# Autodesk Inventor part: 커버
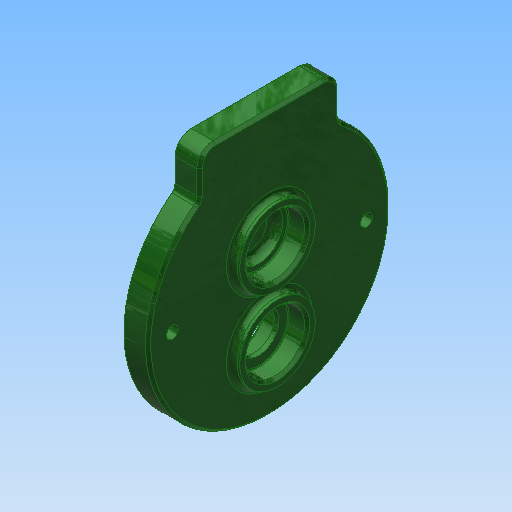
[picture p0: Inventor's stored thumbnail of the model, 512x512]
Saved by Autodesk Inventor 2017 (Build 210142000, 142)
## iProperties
Created: 2016-02
Part Number: 커버
Material: 알루미늄 6061
Document SubType Name: Modeling
Designer: mduedu
Density: 2.71 g/cm^3
Appearance: 매끄러움 - 짙은 산림 녹색
Author: mduedu
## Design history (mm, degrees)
sketch "스케치1"
  geometry: C1 r 45 at (0, 0); 1 further point
  constraints: 1 centre point, 1 coincident
  dimensions: "d0" = 90 diameter of C1
extrude "돌출1" new body sketch "스케치1" distance "d1" = 9; taper "d2" = 0 deg
sketch "스케치2"
  geometry: C1 r 14 at (0, 11); 1 further point
  constraints: 1 centre point, 1 vertical alignment
  dimensions: "d3" = 28 diameter of C1; "d6" = 11 distance of C1.centre point (0, 0)
extrude "돌출2" join sketch "스케치2" distance "d7" = 3; taper "d8" = 0 deg
sketch "스케치3"
  geometry: C1 r 14 at (0, -20); 1 further point
  constraints: 1 centre point, 1 vertical alignment
  dimensions: "d9" = 28 diameter of C1; "d10" = 20 distance of C1.centre point (0, 0)
extrude "돌출3" join sketch "스케치3" distance "d11" = 3; taper "d12" = 0 deg
hole "구멍1" diameter "d15" = 22; stored, may be unused: countersink angle "d19" = 90 deg, drill point angle "d21" = 0 deg; dims "d13" = 10, "d14" = 10, "d16" = 6, "d17" = 4, "d18" = 2, "d20" = 7
hole "구멍2" diameter "d24" = 18; stored, may be unused: countersink angle "d28" = 90 deg, drill point angle "d30" = 0 deg; dims "d25" = 6, "d26" = 4, "d27" = 2, "d29" = 3, "d107" = 10, "d108" = 10
hole "구멍3" diameter "d33" = 22; stored, may be unused: countersink angle "d37" = 90 deg, drill point angle "d39" = 0 deg; dims "d34" = 6, "d35" = 4, "d36" = 2, "d38" = 7, "d73" = 10, "d74" = 10
sketch "스케치7"
  geometry: L1 (-26, 36.729)-(26, 36.729); L2 (26, 36.729)-(26, 53); L3 (26, 53)-(-26, 53); L4 (-26, 53)-(-26, 36.729); A1 r 45 centre (0, 0) between (-26, 36.729) and (26, 36.729) reference; 1 further point
  constraints: 8 end point, 2 parallel, 2 point on circle, 1 horizontal, 1 perpendicular
  dimensions: "d95" = 52 distance of L2.end L3.end; "d97" = 53 distance from line of L3 point (0, 0)
extrude "돌출5" join sketch "스케치7" stored distance "d98" = 10; taper "d99" = 0 deg
sketch "스케치4"
  geometry: C1 r 14 at (0, -20) reference; C2 r 18 at (0, -20); 1 further point
  constraints: 1 centre point, 1 coincident
  dimensions: "d40" = 36 diameter of C2
extrude "돌출4" join sketch "스케치4" distance "d41" = 4; taper "d42" = 0 deg
hole "구멍4" diameter "d45" = 22; stored, may be unused: countersink angle "d49" = 90 deg, drill point angle "d51" = 0 deg; dims "d46" = 6, "d47" = 4, "d48" = 2, "d50" = 7.3, "d102" = 10, "d103" = 10
chamfer "모따기3" distance "d104" = 0.7; stored, may be unused: second distance "d105" = 2, angle "d106" = 30 deg
hole "구멍5" diameter "d54" = 15; stored, may be unused: countersink angle "d58" = 90 deg, drill point angle "d60" = 0 deg; dims "d52" = 10, "d53" = 10, "d55" = 6, "d56" = 4, "d57" = 2, "d59" = 7
fillet "모깎기1" dims "d61" = 0.3
fillet "모깎기2" dims "d62" = 3
chamfer "모따기1" distance "d63" = 1; stored, may be unused: second distance "d64" = 2, angle "d65" = 45 deg
fillet "모깎기6" dims "d88" = 2
sketch "스케치5" dims "d67" = 72
  geometry: 4 further points
  constraints: 2 horizontal alignment, 1 coincident, 5 other
  dimensions: "d71" = 360 deg dimension on point (0, 0) point (-36, 0) (derived)
fillet "모깎기4" dims "d75" = 2
sketch "스케치6"
  geometry: 2 further points
hole "구멍6" sketch "스케치6" at (36, 0), (-36, 0) diameter "d76" = 4.5; stored, may be unused: countersink angle "d80" = 90 deg, drill point angle "d82" = 0 deg; dims "d77" = 6, "d78" = 8, "d79" = 4.6, "d81" = 8
fillet "모깎기7" dims "d100" = 6, "d101" = 3
chamfer "모따기2" distance "d90" = 1; stored, may be unused: second distance "d91" = 2, angle "d92" = 45 deg
node "솔리드1"
node "절단 모서리 투영1"
